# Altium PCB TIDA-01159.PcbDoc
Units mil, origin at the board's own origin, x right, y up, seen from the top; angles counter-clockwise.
Board outline 1460.63 x 1181.1 mil, 2 copper layers (Top Layer, Bottom Layer), stack 62 mil thick; 34 components, 21 nets, 78 pads, 9 vias.
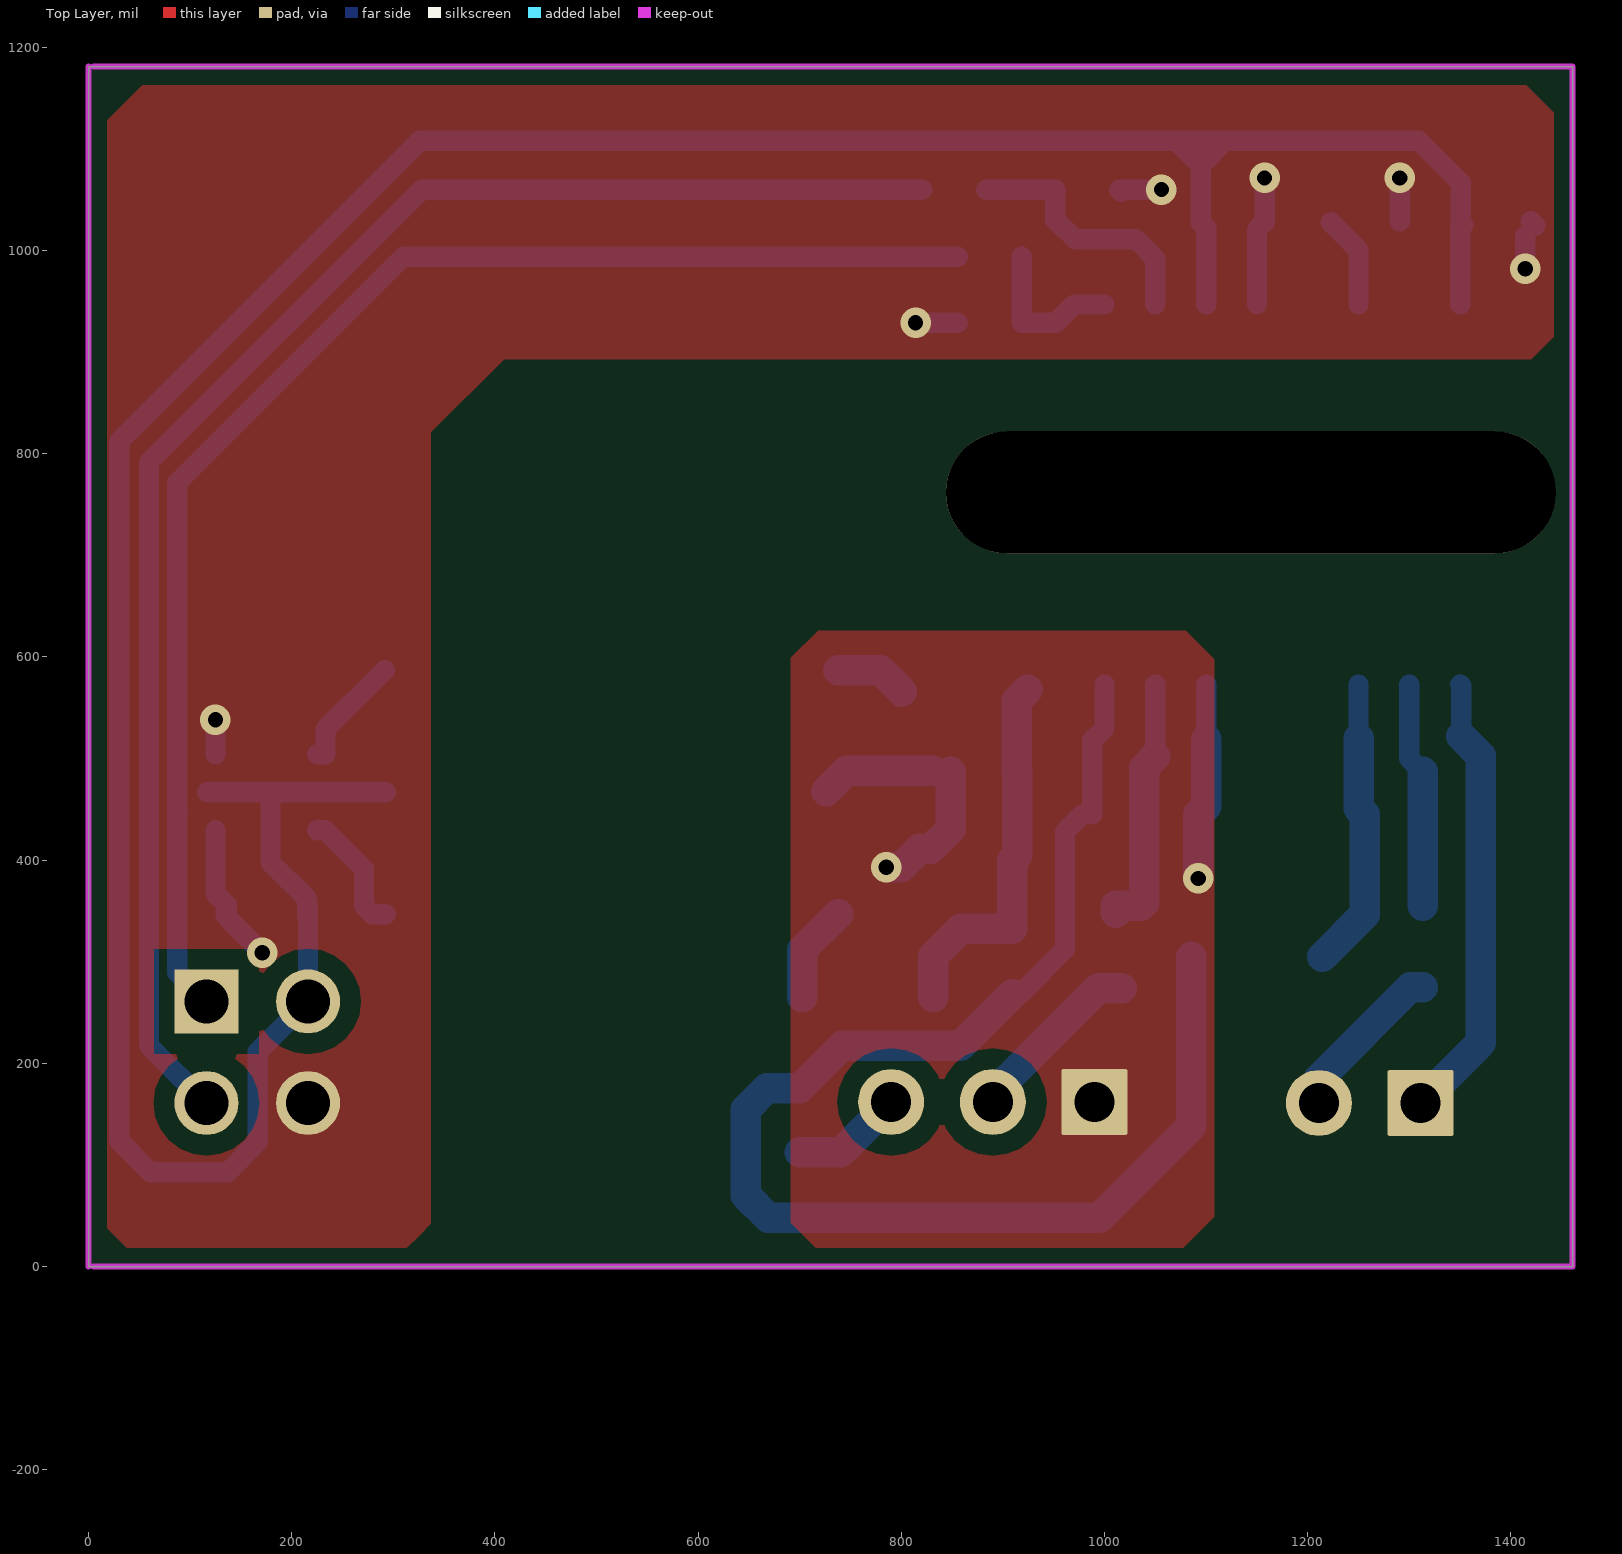
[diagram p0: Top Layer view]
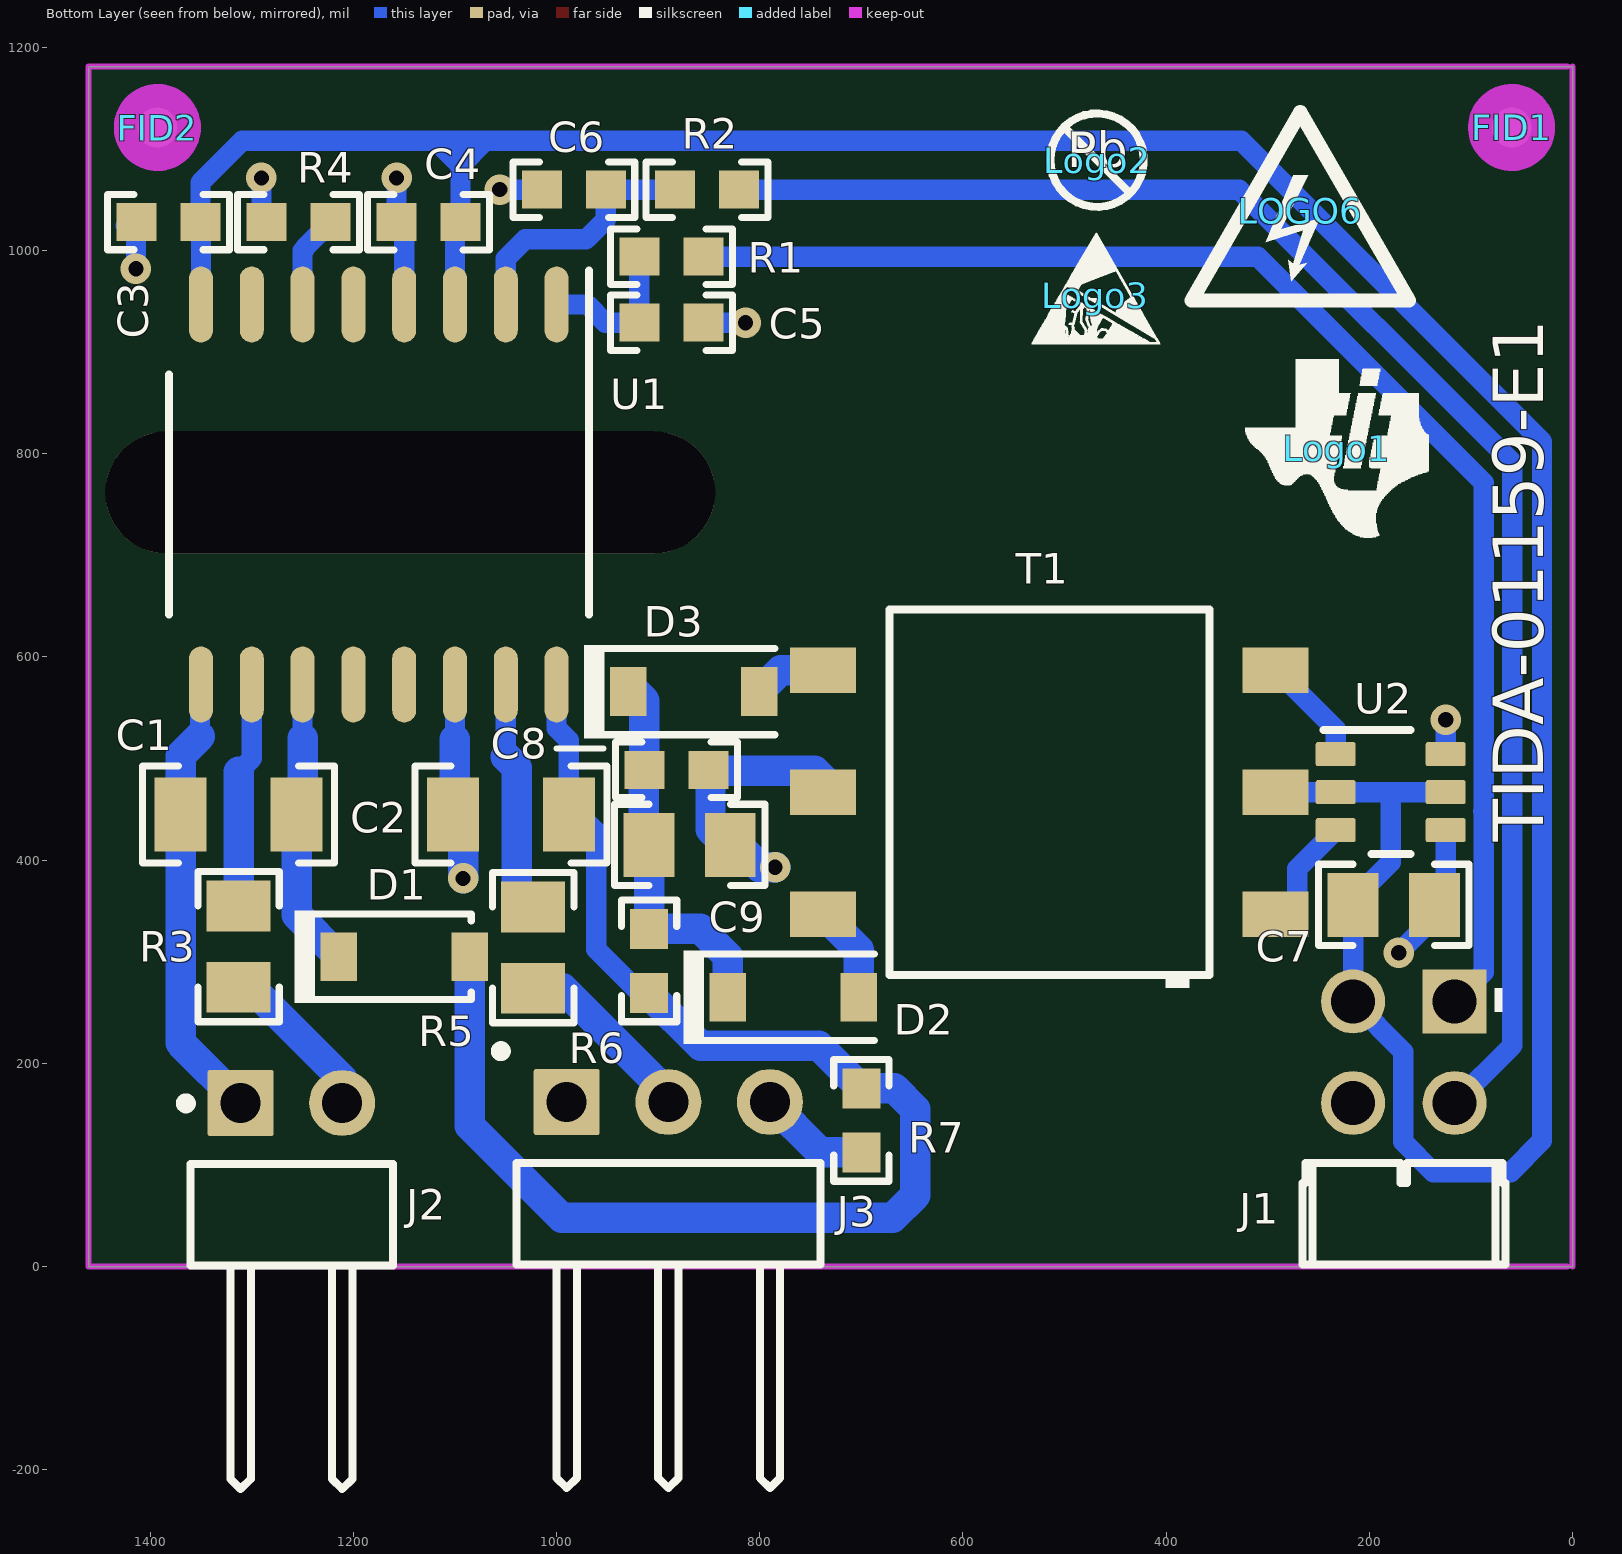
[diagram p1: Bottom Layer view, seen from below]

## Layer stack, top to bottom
Top Solder: solder mask 0.4, Solder Resist, Dk 3.5
Top Layer: signal copper 1.4
Dielectric1: core 59.2, FR-4 High Tg, Dk 4.8
Bottom Layer: signal copper 1.4
Bottom Solder: solder mask 0.4, Solder Resist, Dk 3.5

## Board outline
0,0 0,1181.1 1460.63,1181.1 1460.63,0

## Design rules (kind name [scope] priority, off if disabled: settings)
AcuteAngle [All] p1: minimum=4.50000000000000E+0001 checktracksonly=FALSE
AssemblyTestPointUsage [All] p1: valid=2
Clearance Clearance_Keepouts [((IsTrack Or IsArc) And Not InPoly) And IsFree and IsKeepOut vs ((IsTrack Or IsArc) And Not InPoly) And IsFree and IsKeepOut] p1: gap=20
Clearance Clearance_BoardEdge_MountingHoles [OnCopper and InComponentClass('Mounting Holes') vs IsKeepOut] p2: gap=40
Clearance Clearance_BoardEdge_Poly [OnCopper and InPoly vs IsKeepOut] p3: gap=15
Clearance Clearance_BoardEdge [OnCopper and Not InComponentClass('Logo') and not InComponentClass('FiducialMark') and not InRegion(1000,500,4000,800) and Not IsKeepout vs IsKeepOut] p4: gap=15
Clearance Clearance_Poly [InPolygon] p5: gap=20
Clearance [All] p6: gap=7.87
ComponentClearance ComponentClearance_MountingHoles_FiducialMarks [InComponentClass('Mounting Holes') vs InComponentClass('FiducialMark')] p1: gap=50 collisioncheckmode=3 verticalgap=10 showdistances=FALSE
ComponentClearance ComponentClearance_Shunt [InComponentClass('Header') vs InComponentClass('Shunt')] p2: gap=0 collisioncheckmode=3 verticalgap=0 showdistances=FALSE
ComponentClearance ComponentClearance_Logo [InComponentClass('Logo')] p3: gap=50 collisioncheckmode=3 verticalgap=10 showdistances=FALSE
ComponentClearance ComponentClearance_ScrewToNut [(HasFootprint('NY PMS 440 0025 PH')) vs (HasFootprint('Keystone_1902C'))] p4: gap=5 collisioncheckmode=3 verticalgap=10 showdistances=FALSE
ComponentClearance ComponentClearance_MountingHoles [InComponentClass('Mounting Holes')] p5: gap=200 collisioncheckmode=3 verticalgap=100000 showdistances=FALSE
ComponentClearance ComponentClearance_SmallPassives [HasFootprint('0201*') or HasFootprint('0402*') or HasFootprint('0508') or HasFootprint('0603*') or HasFootprint('0612') or HasFootprint('0805*') or HasFootprint('0815*') or HasFootprint('0830*') or HasFootprint('1206*') or HasFootprint('1210*') or HasFootprint('1808*') or HasFootprint('1812*') or HasFootprint('1825*') or HasFootprint('2010*') or HasFootprint('2220*') or HasFootprint('2225*') or HasFootprint('2512*') or HasFootprint('2728*') or HasFootprint('3518*') vs HasFootprint('0201*') or HasFootprint('0402*') or HasFootprint('0508') or HasFootprint('0603*') or HasFootprint('0612') or HasFootprint('0805*') or HasFootprint('0815*') or HasFootprint('0830*') or HasFootprint('1206*') or HasFootprint('1210*') or HasFootprint('1808*') or HasFootprint('1812*') or HasFootprint('1825*') or HasFootprint('2010*') or HasFootprint('2220*') or HasFootprint('2225*') or HasFootprint('2512*') or HasFootprint('2728*') or HasFootprint('3518*')] p6: gap=20 collisioncheckmode=3 verticalgap=10 showdistances=FALSE
ComponentClearance ComponentClearance_THtoSMT [IsThruComponent vs IsSMTComponent] p7: gap=20 collisioncheckmode=3 verticalgap=20 showdistances=FALSE
ComponentClearance ComponentClearance_THtoTH [IsThruComponent vs IsThruComponent] p8: gap=10 collisioncheckmode=3 verticalgap=10 showdistances=FALSE
ComponentClearance [All] p9: gap=20 collisioncheckmode=3 verticalgap=10 showdistances=FALSE
DiffPairsRouting [All] p1: maxlimit=100 minlimit=10 mostfreqgap=10 toplayer_minwidth=15 toplayer_maxwidth=15 toplayer_prefwidth=15 bottomlayer_minwidth=15 bottomlayer_maxwidth=15 bottomlayer_prefwidth=15 maxuncoupledlength=1000
FabricationTestPointUsage TestPointUsage [All] p1: valid=2 allowmultiple=FALSE
FabricationTestpoint Testpoint [All] p1: side=3 testpointundercomponent=TRUE minsize=40 maxsize=100 preferedsize=60 minholesize=0 maxholesize=40 preferedholesize=32 testpointgrid=1 allowsidetop=TRUE allowsidebottom=TRUE usegrid=TRUE gridtolerance=0.01
FanoutControl Fanout_LCC [IsLCC] p1: bgadir=Out bgaviamode=Centered fanoutstyle=Auto fanoutdirection=Alternating viagrid=1 // Fanout_LCC (Default Rule)
FanoutControl Fanout_BGA [IsBGA] p2: bgadir=Out bgaviamode=Centered fanoutstyle=Auto fanoutdirection=Alternating viagrid=1 // Fanout_BGA (Default Rule)
FanoutControl Fanout_Default [All] p4: bgadir=Out bgaviamode=Centered fanoutstyle=Auto fanoutdirection=Alternating viagrid=1 // Fanout_Default (Default Rule)
FanoutControl Fanout_Small [(CompPinCount < 5)] p5: bgadir=Out bgaviamode=Centered fanoutstyle=Auto fanoutdirection=OutThenIn viagrid=1 // Fanout_Small (Default Rule)
HoleSize [All] p1: absolutevalues=TRUE maxlimit=251 minlimit=8 maxpercent=80.000 minpercent=20.000
MinimumAnnularRing MinimumAnnularRing_ThermalPadVias [IsVia and InAnyComponent] p1: minimumring=5.91
MinimumAnnularRing [All] p2: minimumring=6
MinimumSolderMaskSliver MinimumSolderMaskSliver_Logo [InComponentClass('Logo') vs InComponentClass('Logo')] p1: minsoldermaskwidth=0.7
MinimumSolderMaskSliver [All] p2: minsoldermaskwidth=3.94
PlaneConnect [All] p1: planeconnectstyle=Relief reliefexpansion=10 reliefentries=4 reliefconductorwidth=10 reliefairgap=10
PolygonConnect [All] p1: connectstyle=Direct reliefconductorwidth=10 reliefentries=4 polygonreliefangle="90 Angle" airgapwidth=10
RoutingVias ThermalPadVias [IsVia and InAnyComponent] p1: holewidth=7.87 width=19.68 viastyle="Through Hole" minholewidth=7.87 minwidth=19.68 maxholewidth=12.99 maxwidth=23.62
RoutingVias [All] p2: holewidth=12 width=24 viastyle="Through Hole" minholewidth=7.87 minwidth=26 maxholewidth=40 maxwidth=65
SilkToBoardRegionClearance [Not ((IsComment or IsDesignator) And (Hide <> 'False')) and not InRegion(1000,500,4000,800)] p1:
SilkToSilkClearance SilkToSilkClearance_Pb-FreeLogo [(HasFootprint('Pb-Free_Overlay_Medium') OR HasFootprint('Pb-Free_Overlay_Small')) vs (HasFootprint('Pb-Free_Overlay_Medium') OR HasFootprint('Pb-Free_Overlay_Small'))] p1: silktosilkclearance=0
SilkToSilkClearance [All] p2: silktosilkclearance=4
SilkToSolderMaskClearance "Silk to Solder Mask Opening" [All] p1: minsilkscreentomaskgap=4 clearancetoexposedcopper=FALSE
SolderMaskExpansion [All] p1: expansion=1.97
UnpouredPolygon [All] p1: allowunpoured=FALSE
Width [All] p1: maxlimit=40 minlimit=6 preferedwidth=20 checkconnectedcopper=TRUE
14 further rules are at their usual default settings.

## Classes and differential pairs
component class Header: J1
component class Logo: Logo1
component class TIDA-01159_Hardware: FID1 FID2 Logo1 Logo2 Logo3 LOGO6 ZZ2 ZZ3 ZZ4
component class FiducialMark: FID1 FID2
component class AssemblyNote: ZZ2 ZZ3 ZZ4
component class TIDA-01159_Sheet1: C1 C2 C3 C4 C5 C6 C7 C8 C9 D1 D2 D3 J1 J2 J3 R1 R2 R3 R4 R5 R6 R7 T1 U1 U2

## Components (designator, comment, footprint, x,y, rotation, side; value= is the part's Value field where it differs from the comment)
C1 "CGA5L3X7T2E224K160AE" 1206 1313,445 r0 bottom
C2 "CGA5L3X7T2E224K160AE" 1206 1045,445 r0 bottom
C3 "885012106018" 0603 1382,1028 r180 bottom
C4 "C0603X104K3RACTU" 0603 1126,1028 r0 bottom
C5 "06035A220JAT2A" 0603 887,929 r180 bottom
C6 "06035A220JAT2A" 0603 983,1060 r0 bottom
C7 "GRM21BZ71E106KE15L" 0805_HV 176,356 r0 bottom
C8 "8.850122061e+011" 0603 882,489 r0 bottom
C9 "GRM21BZ71E106KE15L" 0805_HV 869,415 r0 bottom
D1 "UFM15PL-TP" SOD-123FL 1150,305 r180 bottom
D2 "1N5819HW-7-F" SOD-123 767,265 r180 bottom
D3 "1N5819HW-7-F" SOD-123 865,566 r180 bottom
FID1 "Fiducial" Fiducial10-20 60,1121.1 r90 bottom
FID2 "Fiducial" Fiducial10-20 1392.95,1121.1 r180 bottom
J1 "61300421021" Wurth_61300421021 166,211 r270 bottom
J2 "TSW-102-08-G-S-RA" TSW-102-08-G-S-RA 1259,162 r180 bottom
J3 "TSW-103-08-G-S-RA" TSW-103-08-G-S-RA 890,162 r180 bottom
Logo1 "Texas Instruments" TI_Symbol_Overlay_Small 232,805 r180 bottom
Logo2 "Pb-Free Symbol" Pb-Free_Overlay_Small 468,1089 r180 bottom
Logo3 "ESD Susceptible" ESD_Overlay_Small 470,956 r180 bottom
LOGO6 "DANGER HIGH VOLTAGE" IEC_HighVoltage_Small 268,1039 r180 bottom
R1 "CRCW0603100RFKEA" 0603 887,994 r0 bottom
R2 "CRCW0603100RFKEA" 0603 852,1060 r0 bottom
R3 "CRCW08050000Z0EA" 0805_HV 1313,315 r270 bottom
R4 "RT0603BRD074K75L" 0603 1254,1028 r180 bottom
R5 "CRCW08050000Z0EA" 0805_HV 1023,314 r270 bottom
R6 "CRCW06030000Z0EA" 0603 909,301 r270 bottom
R7 "CRCW06030000Z0EA" 0603 700,144 r270 bottom
T1 "750342879" WURTH_750342879 515,467 r0 bottom
U1 "UCC21520DW" DW0016A_N 1175,760 r270 bottom
U2 "SN6505BDBVR" DBV0006A_N 179,467 r180 bottom
ZZ2 "These assemblies are ESD sensitive, ESD precautions shall be observed." AssemblyNote -80,1683.6 r0 top
ZZ3 "These assemblies must be clean and free from flux and all contaminants. Use of no clean flux is not acceptable." AssemblyNote -80,1595.05 r0 top
ZZ4 "These assemblies must comply with workmanship standards IPC-A-610 Class 2, unless otherwise specified." AssemblyNote -80,1506.49 r0 top

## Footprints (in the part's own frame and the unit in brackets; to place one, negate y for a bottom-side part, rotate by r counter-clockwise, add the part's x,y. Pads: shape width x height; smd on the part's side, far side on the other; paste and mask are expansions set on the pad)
0603 [mm] "0603 from SM-752 data"
  rect 1x0.95 smd: 1(-0.8,0) 2(0.8,0)
  silkscreen extent -1.52,-0.69 1.52,0.69, body extent -0.87,-0.47 0.87,0.47, height 1
0805_HV [mil] "0805 with 30mil clearance between pads"
  rect 50x63 smd: 1(-40,0) 2(40,0)
  silkscreen extent -74,-40 74,40, body extent -43,-29 43,29, height 57
1206 [mm] "1206 from SM-752 data"
  rect 1.3x1.85 smd: 1(-1.45,0) 2(1.45,0)
  silkscreen extent -2.4,-1.21 2.4,1.21, body extent -1.7,-0.9 1.7,0.9, height 1.35
AssemblyNote [mil] "Assembly Note"
DBV0006A_N [mm] "SOT23, 6-Leads, Body 2.9x1.6mm, Pitch 0.95mm, Lead Span 2.8mm, IPC Medium Density"
  rrect17% 1x0.6 smd: 1(-1.375,0.95) 2(-1.375,0) 3(-1.375,-0.95) 4(1.375,-0.95) 5(1.375,0) 6(1.375,0.95)
  silkscreen extent -1.68,-1.55 0.5,1.55, body extent -1.42,-1.46 1.42,1.46, height 1.12
DW0016A_N [mm] "SOIC, 16-Leads, Body 10.3x7.5mm, Pitch 1.27mm, IPC Medium Density"
  oval 1.9x0.6 smd: 1(-4.75,4.445) 2(-4.75,3.175) 3(-4.75,1.905) 4(-4.75,0.635) 5(-4.75,-0.635) 6(-4.75,-1.905) 7(-4.75,-3.175) 8(-4.75,-4.445) 9(4.75,-4.445) 10(4.75,-3.175) 11(4.75,-1.905) 12(4.75,-0.635) 13(4.75,0.635) 14(4.75,1.905) 15(4.75,3.175) 16(4.75,4.445)
  silkscreen extent -5.6,-5.25 3,5.25, body extent -5.14,-5.13 5.14,5.13, height 2.54
ESD_Overlay_Small [mil]
  silkscreen extent -62,-48 64,61
Fiducial10-20 [mm]
  round 1 smd mask+0.5: 1(0,0)
  Top Layer keep-out circle w1.178: c0,0 r0.5
IEC_HighVoltage_Small [mil]
  silkscreen extent -107,-88 107,97
Pb-Free_Overlay_Small [mil]
  silkscreen extent -46,-46 46,46
SOD-123 [mm] "On Semi recommended land pattern"
  rect 0.915x1.22 smd: 1(-1.637,0) 2(1.637,0)
  silkscreen extent -2.74,-1.17 2.03,1.17, body extent -1.93,-0.9 1.93,0.9, height 1.35
SOD-123FL [mm] "Copied from SOD-123"
  rect 0.915x1.22 smd: 1(-1.637,0) 2(1.637,0)
  silkscreen extent -2.74,-1.16 1.68,1.16, body extent -1.9,-0.9 1.9,0.9, height 1
TI_Symbol_Overlay_Small [mil]
  silkscreen extent -90,-88 91,88
TSW-102-08-G-S-RA [mm] "Samtec Right Angle Header"
  rrect6% 1.65x1.65 hole 1: 1(-1.321,-0.025)
  round 1.65 hole 1: 2(1.219,-0.025)
  silkscreen extent -2.82,-9.68 2.49,0.09, body extent -2.59,-9.93 2.49,0.29, height 3.05
TSW-103-08-G-S-RA [mm] "Samtec Right Angle Header"
  rrect6% 1.65x1.65 hole 1: 1(-2.54,0)
  round 1.65 hole 1: 2(0,0) 3(2.54,0)
  silkscreen extent -4.31,-9.65 3.81,1.39, body extent -3.81,-9.91 3.81,0.32, height 3.05
WURTH_750342879 [mm] "SMD, 6-Leads, Body 9.14x8mm, Pitch 3.05mm"
  rect 1.649x1.14 smd: 1(-5.655,3.05) 2(-5.655,0) 3(-5.655,-3.05) 4(5.655,-3.05) 5(5.655,0) 6(5.655,3.05)
  silkscreen extent -4,-4.57 4,4.9, body extent -6.35,-4.57 6.35,4.57, height 7.83
Wurth_61300421021 [mm] "Header, 2.54mm, 2x2, R/A, TH"
  rect 1.6x1.6 hole 1.1: 1(-1.27,1.27)
  round 1.6 hole 1.1: 2(1.27,1.27) 3(-1.27,-1.27) 4(1.27,-1.27)
  silkscreen extent -1.6,-2.54 5.31,2.54, body extent -1.59,-2.54 11.31,2.54, height 5.08

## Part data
C1 C2: "CAP, CERM, 0.22 µF, 250 V, +/- 10%, X7T, 1206"
C3: "CAP, CERM, 2.2 µF, 16 V, +/- 20%, X5R, 0603"
C4: "CAP, CERM, 0.1 µF, 25 V, +/- 10%, X7R, 0603"
C5 C6: "CAP, CERM, 22 pF, 50 V, +/- 5%, C0G/NP0, 0603"
C7 C9: "CAP, CERM, 10 µF, 25 V, +/- 10%, X7R, 0805"
C8: "CAP, CERM, 0.1 µF, 50 V, +/- 10%, X7R, 0603"
D1: "Diode, Ultrafast, 600 V, 1 A, SOD-123FL"
D2 D3: "Diode, Schottky, 40 V, 1 A, SOD-123"
FID1 FID2: "Fiducial mark.  There is nothing to buy or mount."
J1: "Header, 2.54mm, 2x2, Gold, R/A, TH"
J2: "Header, 100mil, 2x1, Gold, R/A, TH"
J3: "Header, 100mil, 3x1, Gold, R/A, TH"
Logo1: library part TI_Logo, "Texas Instrument Corporate Signature"
Logo2: library part Pb-Free
Logo3: library part ESD_Susceptible, "ESD Susceptible Symbol"
LOGO6: library part IEC_HighVoltage, "IEC 61010-1 High Voltage Warning"
R1 R2: "RES, 100, 1%, 0.1 W, 0603"
R3 R5: "RES, 0, 5%, 0.125 W, 0805"
R4: "RES, 4.75 k, 0.1%, 0.1 W, 0603"
R6 R7: "RES, 0, 5%, 0.1 W, 0603"
T1: "Transformer, 50 uH, SMT"
U1: "4A/6A, 5KVrms Dual Isolated-channel Universal Gate Driver, DW0016A"
U2: "LOW-NOISE 1A TRANSFORMER DRIVERS FOR ISOLATED POWER SUPPLIES, DBV0006A"
ZZ2 ZZ3 ZZ4: library part AssemblyNote

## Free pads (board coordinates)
  oval 600x120 hole 120 slot 600 at 0 deg unplated mask+5: 0(1144,762)

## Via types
v1: diameter 30, hole 15, Top Layer to Bottom Layer, tented both sides, 9 vias

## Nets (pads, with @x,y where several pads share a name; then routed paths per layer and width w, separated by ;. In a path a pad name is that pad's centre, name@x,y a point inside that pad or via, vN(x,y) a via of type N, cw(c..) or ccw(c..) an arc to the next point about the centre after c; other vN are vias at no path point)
AUX_12V: C2.1 D1.2 R6.2 R7.1 U1.16 | length 1378.7
  Bottom Layer w20: R6.2@918.35,269.5 961,312.16 961,428.09 C2.1@977.91,445 ; C2.1 987.91,517.91 1000,530 U1.16
  Bottom Layer w30: R6.2@909,268.16 858.2,217.35 741.86,217.35 R7.1 667.5,175.5 647,155 647,70 669,48 995,48 1085.53,138.53 D1.2
GD_HS: J2.2 R3.2 | length 163.3
  Bottom Layer w30: J2.2 1211,185 1301,275 R3.2
GD_LS: J3.2 R5.2 | length 178.1
  Bottom Layer w30: J3.2 890,170 994,274 R5.2@1017,274
HV_AUX_12V: J3.3 R7.2 | length 110.5
  Bottom Layer w30: R7.2 740.5,112.5 J3.3
HV_GND: C2.2 C8.1 C9.1 J3.1 T1.5 U1.14 | length 433.3
  Bottom Layer w20: 1100,519 U1.14
  Bottom Layer w30: T1.5@725.92,468 745.92,488 C8.1@831.5,488 ; v1(785,393) 800,393 818,411 C9.1@817.5,411.5 ; C9.1@829,411 848.5,430.5 C8.1@848.5,487 ; v1(1092.09,382.09) 1092.09,445 1100,452.91 1100,519
HV_HS_PWM: J1.1 R1.1 | length 1383.3
  Bottom Layer w20: J1.1 87.31,289.69 87.31,447.64 87.97,448.3 87.31,448.96 87.31,771.43 309.87,994 R1.1
HV_LS_PWM: J1.2 R2.1 | length 1526.2
  Bottom Layer w20: J1.2 59.43,217.57 59.43,791.43 328,1060 R2.1
HV_SNODE: C1.2 J2.1 U1.9 | length 444.8
  Bottom Layer w20: U1.9 1351,571.99 1351,522
  Bottom Layer w30: J2.1 1370.09,220.09 C1.2 1370.09,502.91 1351,522
LV_AUX_5V: C3.2 C4.1 C7.2 J1.3 T1.2 U1.3 U1.8 U2.2 U2.5 | length 3228.5
  Bottom Layer w20: U2.5@116.87,467 U2.5 179,467 ; C7.2@215,345 215,362 179,398 179,467 ; C7.2 J1.3 166.63,211.63 166.63,122.63 137,93 60.84,93 30.13,123.72 30.13,812.13 326,1108 1070.02,1108 ; T1.2 U2.2 179,467 ; U1.3 1100,1022.5 C4.1 1094.5,1083.51 ; U1.8@1350.5,947.5 U1.8 1350,1022.5 C3.2@1353,1025.5 ; C3.2 1350.5,1066.74 1309.25,1108 1118.99,1108 ; 1070.02,1108 1096,1108 ; 1070.02,1108 1094.5,1083.51 ; 1094.5,1083.51 1118.99,1108 ; 1094.5,1083.51 1094.5,1106.5 1096,1108 ; 1096,1108 1118.99,1108
NetC1_1: C1.1 D1.1 U1.11 | length 287.6
  Bottom Layer w20: 1250,520 U1.11
  Bottom Layer w30: D1.1 1255.91,346.45 C1.1 1250,450.91 1250,520
NetC5_1: C5.1 R1.2 U1.1 | length 154
  Bottom Layer w20: R1.2 C5.1 952,929 970.01,947.01 U1.1
NetC6_1: C6.1 R2.2 U1.2 | length 256.9
  Bottom Layer w20: R2.2 C6.1 951.5,1030.5 971,1011 1031,1011 1050,992 U1.2
NetC8_2: C8.2 C9.2 D2.1 D3.1 R6.1 | length 371.3
  Bottom Layer w30: D2.1 831.47,305.47 858.5,332.5 R6.1 909,400 914,405 C8.2@914,489 ; C8.2 913.5,557.03 D3.1@924.47,568
NetD2_2: D2.2 T1.6 | length 96.5
  Bottom Layer w30: D2.2 702.53,311.82 T1.6
NetD3_2: D3.2 T1.4 | length 71.6
  Bottom Layer w30: T1.4 779.45,587.08 D3.2
NetR3_1: R3.1 U1.10 | length 223.4
  Bottom Layer w20: U1.10 1300,500 1313,487
  Bottom Layer w30: R3.1 1313,487
NetR4_2: R4.2 U1.6 | length 92.4
  Bottom Layer w20: R4.2 1247.94,1002.57 1247.94,1001.9 1250,999.83 U1.6
NetR5_1: R5.1 U1.15 | length 253.4
  Bottom Layer w20: 1050,502 U1.15
  Bottom Layer w30: R5.1@1011,348.47 R5.1@1014.27,351.73 ; R5.1@1011,355 1036,355 1039,358 1039,491 1050,502
NetT1_1: T1.1 U2.3 | length 123
  Bottom Layer w20: U2.3@225.13,429.6 U2.3 271,391.73 271,355 279.08,346.92 T1.1
NetT1_3: T1.3 U2.1 | length 114.8
  Bottom Layer w20: U2.1@225.13,504.4 U2.1 233.13,528.85 T1.3@291.36,587.08
SGND: C3.1 C4.2 C5.2 C6.2 C7.1 J1.4 R4.1 U1.4 U2.4 U2.6 | length 480.2
  Bottom Layer w20: U2.4 124.87,367.13 C7.1@135,357 ; U2.6 v1(124.87,538.13) ; C7.1@135,345 C7.1@135,357 ; v1(171,309) 136,344 C7.1 C7.1@135,357 ; v1(814,929) C5.2 ; C6.2@1016.5,1058 C6.2 v1(1056,1060) ; U1.4 1150,1020.5 C4.2 v1(1157.5,1071.5) ; R4.1@1290.5,1029 v1(1290.5,1071.5) ; v1(1414,982) C3.1@1414,1014.5 ; C3.1@1419.5,1029 C3.1@1424,1024.5
pads on no net: FID1.1 FID2.1 U1.5 U1.7 U1.12 U1.13

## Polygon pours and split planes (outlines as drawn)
no net on Top Solder "M9 Title Sheet-No Net" (solid): 1280,827.04 1280,697 1382.95,697 1382.95,807 1382.95,826.98
no net on Top Solder "M9 Title Sheet-No Net" (solid): 1460,827 1460,697 576,697 576,0 449,0 449,827
no net on Bottom Solder "M9 Title Sheet-No Net" (solid): 1382.95,827 1280,827 1280,697 1382.95,697 1382.95,807
no net on Bottom Solder "M9 Title Sheet-No Net" (solid): 448,827 1460.63,827 1460.63,697 578,697 578,0.46 448,0.46
SGND on Top Layer "M9 Title Sheet-No Net" (solid, remove dead copper, pour order 9): 5,112 5,51 56,0 65,0 295,0 325,30 337,42 337,386 337,821 409,893 881.16,893 1420,893 1447,920 1447,1131 1397,1181 71,1181 5,1115
HV_GND on Top Layer "M9 Title Sheet-No Net" (solid, remove dead copper, pour order 8): 691,599 691,43 734,0 1059,0 1108,49 1108,598 1080,626 921,626 718,626

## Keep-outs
Keep-Out Layer:
  lines w6: 0,0 0,1181.1 ; 5,0 1460.63,0 1460.63,1181.1 5,1181.1
  text ".Layer_Name" at 362,-1164 h60

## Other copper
Top Layer:
  text ".Layer_Name" at 362,-1164 h60
Bottom Layer:
  text ".Layer_Name" at 362,-1164 h60

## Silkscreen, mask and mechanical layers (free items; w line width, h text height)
Top Overlay:
  text ".Layer_Name" at 362,-1164 h60
Bottom Overlay:
  lines w6: 954,510 1000,510
  text "TIDA-01159-E1" at 29,418 h50 r270
  text ".Layer_Name" at 362,-1164 h60
Top Paste:
  text ".Layer_Name" at 362,-1164 h60
Bottom Paste:
  text ".Layer_Name" at 362,-1164 h60
Top Solder:
  text ".Layer_Name" at 362,-1164 h60
  text ".Layer_Name" at 362,-1164 h60
Bottom Solder:
  text ".Layer_Name" at 362,-1164 h60
Drill Guide:
  text ".Layer_Name" at 362,-1164 h60
M1 Board Outline:
  the board outline again, w10
M2 Board Dimensions:
  rectangle: -215,-580.51 -90,-455.51
  rectangle: -90,-705.51 285,-580.51
  lines w7: -215,-580.51 785,-580.51 ; -90,-705.51 -90,-455.51 ; 35,-705.51 35,-455.51 ; 285,-705.51 285,-455.51 ; 535,-705.51 535,-455.51 ; -215,-705.51 785,-705.51 785,-455.51 -215,-455.51 -215,-705.51
M3 3D STEP Top:
  text ".Layer_Name" at 362,-1164 h60
M4 3D STEP Bottom:
  text ".Layer_Name" at 362,-1164 h60
M5 Assembly Top:
  lines w10: -507,-1235.68 6093,-1235.68 ; -507,-1032.34 6095,-1032.34 ; -507,-829.01 -507,-1439.01 3498,-1439.01 6095,-1439.01 6095,-829.01 -506.5,-829.01 -506.5,-1439.01 1069,-1439.01 ; 1958,-1439.01 1958,-829.01 ; 3225,-1032.34 3225,-829.01 ; 4065,-1032.34 4065,-829.01 ; 4687,-1445.51 4687,-1242.68
  text "COMPONENTS MARKED 'DNP' SHOULD NOT BE POPULATED." at 938.5,-624.01 h60
  text "ASSEMBLY VARIANT:" at 938,-739.51 h60
  text ".VariantName" at 1974,-739.51 h60
  text "PCB VIEWED FROM TOP SIDE" at -443.5,-961.18 h60
  text "BOARD #:" at 2033,-961.18 h60
  text ".PRJ_Number" at 2578.5,-961.18 h60
  text "REV:" at 3423,-961.18 h60
  text ".PCB_Rev" at 3714.5,-961.18 h60
  text "SVN REV:" at 4261,-961.18 h60
  text ".VersionControl_RevNumber" at 4767,-961.18 h60
  text ".LAyer_Name" at 332,-1161 h60
  text "TID #:" at 2033,-1164.51 h60
  text ".TID" at 2578.5,-1164.51 h60
  text "PLOT NAME =" at -443.5,-1369.85 h60
  text ".plot_File_Name" at 362,-1369.85 h60
  text "GENERATED    :" at 2035,-1369.85 h60
  text ".Print_Date" at 2904.5,-1369.85 h60
  text ".Print_Time" at 3633.5,-1369.85 h60
  text "TEXAS INSTRUMENTS" at 4898,-1369.85 h60
M6 Assembly Bottom:
  lines w10: -507.5,-1032.84 6094.5,-1032.84 ; -505.5,-1236.18 6094.5,-1236.18 ; 900.5,-1446.01 900.5,-1243.18 ; 1522.5,-1032.84 1522.5,-829.51 ; 2362.5,-1032.84 2362.5,-829.51 ; 3629.5,-1439.51 3629.5,-829.51 ; 4518.5,-1439.51 6094,-1439.51 6094,-829.51 -507.5,-829.51 -507.5,-1439.51 2089.5,-1439.51 6094.5,-1439.51 6094.5,-829.51
  text "COMPONENTS MARKED 'DNP' SHOULD NOT BE POPULATED." at 5887,-623.51 h60
  text ".VariantName" at 4843,-739.51 h60
  text "ASSEMBLY VARIANT:" at 5882,-739.51 h60
  text ".VersionControl_RevNumber" at 820.5,-961.68 h60
  text "SVN REV:" at 1326.5,-961.68 h60
  text ".PCB_Rev" at 1873,-961.68 h60
  text "REV:" at 2164.5,-961.68 h60
  text ".PRJ_Number" at 3009,-961.68 h60
  text "BOARD #:" at 3554.5,-961.68 h60
  text "PCB VIEWED FROM BOTTOM SIDE" at 6031,-961.68 h60
  text ".LAyer_Name" at 5302,-1150 h60
  text ".TID" at 3009,-1165.01 h60
  text "TID #:" at 3554.5,-1165.01 h60
  text "TEXAS INSTRUMENTS" at 689.5,-1370.35 h60
  text ".Print_Time" at 1954,-1370.35 h60
  text ".Print_Date" at 2683,-1370.35 h60
  text "GENERATED    :" at 3552.5,-1370.35 h60
  text ".plot_File_Name" at 5225.5,-1370.35 h60
  text "PLOT NAME =" at 6031,-1370.35 h60
M9 Title Sheet:
  drawing of 57 lines, arcs and shapes, not listed
  text "1" at 524.84,7730.99 h70
  text "2" at 3020.5,7730.99 h70
  text "3" at 5509.84,7730.99 h70
  text "4" at 8016.51,7730.99 h70
  text "5" at 10515.5,7730.99 h70
  text "6" at 13020.5,7730.99 h70
  text "A" at -631.5,6587.99 h70
  text "A" at 14168.5,6587.99 h70
  text "B" at -631.5,4207.99 h70
  text "B" at 14168.5,4207.99 h70
  text "C" at -631.5,1832.99 h70
  text "C" at 14168.5,1832.99 h70
  text "PROJECT TITLE:" at 11128.5,-28.01 h45
  text ".PRJ_Title" at 11178.5,-161.34 h70
  text "DESIGNED FOR:" at 11128.5,-329.01 h45
  text ".PRJ_Customer" at 11178.5,-469.01 h70
  text "D" at -631.5,-537.01 h70
  text "D" at 14168.5,-537.01 h70
  text "FILE NAME:" at 11128.5,-629.01 h45
  text ".PCB_File_Name_No_Path" at 11178.5,-749.01 h70
  text "Texas Instruments (TI) and/or its licensors do not warrant the accuracy or completeness of this specification" at 6159,-910.85 h45
  text "ENGINEER:" at 11128.5,-919.01 h45
  text "LAYOUT BY:" at 12633.5,-919.01 h45
  text "or any information contained therein. TI and/or its licensors do not warrant that this design will meet" at 6114.02,-1023.52 h45
  text ".PRJ_Engineer" at 11178.5,-1074 h70
  text ".PCB_Layout" at 12684,-1074 h70
  text "the specifications, will be suitable for your application or fit for any particular purpose, or will operate in" at 6114.02,-1136.18 h45
  text "ALTIUM DESIGNER VERSION:" at 12633.5,-1229.01 h45
  text "an implementation. TI and/or its licensors do not warrant that the design is production worthy. You should" at 6114.02,-1248.85 h45
  text "completely validate and test your design implementation to confirm the system functionality for your application." at 6159,-1361.51 h45
  text ".print_Scale" at 11178.5,-1362.34 h70
  text ".Application_BuildNumber" at 12684,-1362.34 h70
  text "1" at 524.84,-1569.01 h70
  text "2" at 3020.5,-1569.01 h70
  text "3" at 5509.84,-1569.01 h70
  text "4" at 8016.51,-1569.01 h70
  text "5" at 10515.5,-1569.01 h70
  text "6" at 13020.5,-1569.01 h70
M10 Fab Notes:
  drawing of 191 lines, arcs and shapes, not listed
  text "DESIGN INFORMATION" at 12171.52,6384.49 h60
  text "(REFER ALSO ARRAY/PANEL PROFILING INFORMATION)" at 11809.96,6222.77 h60
  text "BOARD SIZE" at 11123.96,6218.49 h60
  text "X" at 12091.96,6090.67 h60
  text "30MM" at 12327.5,6083.49 h60
  text "37.1MM" at 11578,6080 h60
  text "Number of Layers :" at 11541.96,5983.49 h60
  text "2" at 12636.77,5973.49 h60
  text "MIN. TRACK WIDTH:" at 11541.96,5844.49 h60
  text "20" at 12611.5,5844.89 h60
  text "MIL" at 12792.96,5844.49 h60
  text "MIN. CLEARANCE:" at 11541.96,5712.49 h60
  text "7.87" at 12560,5712 h60
  text "MIL" at 12810.5,5685.89 h60
  text "MIN. VIA PAD SIZE:" at 11541.96,5580.49 h60
  text "30" at 12622.5,5580.89 h60
  text "MIL" at 12810.5,5557.89 h60
  text "0.19mm (7.5MIL)" at 12236.96,5438.78 h60
  text "EXTERNAL" at 12973.5,5438.89 h60
  text "MINIMUM ANNULAR RING" at 11212.73,5434.49 h60
  text "PER" at 11412.73,5316.49 h60
  text "IPC-D-275 CLASS 2 LEVEL C" at 11632.73,5316.49 h60
  text "MIL, HOLES" at 13120.96,5204.2 h60
  text "+/-" at 12728.5,5203.49 h60
  text "+/-" at 13582.5,5203.49 h60
  text "REGISTRATION TOLERANCES:" at 11212.73,5198.49 h60
  text "METAL" at 12412.5,5198.49 h60
  text "5" at 12988.7,5198.49 h60
  text "3" at 13821.7,5198.49 h60
  text "MIL" at 13937.96,5198.49 h60
  text "IMPEDENCE CONTROLLED BOARD:NO" at 11245.5,5049.49 h60
  text "MATERIAL:" at 11121.96,4826.03 h60
  text "FR-4 High Tg" at 12108.4,4685.7 h60
  text "FR-408" at 11542.96,4677.13 h60
  text "OTHER" at 13030.96,4677.13 h60
  text "X" at 11946.5,4675.49 h60
  text "THICKNESS:" at 11123.5,4520.49 h60
  text "63 MIL (1.6mm) +/-10%" at 11782.5,4515.49 h60
  text "OTHER" at 13147.96,4510.13 h60
  text "X" at 11647.5,4507.49 h60
  text "TOLERANCE:" at 11196.73,4352.13 h60
  text "X" at 12036.03,4352.13 h60
  text "ANSI IPC-6012 TYPE 3 CLASS 2" at 12222.98,4352.13 h60
  text "OTHER +/-" at 12222.96,4196.13 h60
  text "BOW & TWIST:" at 11196.73,4039.13 h60
  text "X" at 12036.03,4039.13 h60
  text "ANSI IPC-6012 TYPE 3 CLASS 2" at 12222.98,4039.13 h60
  text "OTHER +/-" at 12222.96,3880.62 h60
  text "DRILLING:" at 11121.96,3742.13 h60
  text "REFERENCE:" at 11196.73,3625.13 h60
  text "X" at 11844.96,3625.13 h60
  text "AS SHOWN" at 12031.96,3625.13 h60
  text "X" at 12745.96,3625.13 h60
  text "NC_DRILL FILES" at 12882.96,3625.13 h60
  text "PTH MIN COPPER THICKNESS:" at 11196.73,3467.13 h60
  text "X" at 12546.96,3467.13 h60
  text "1MIL" at 12683.96,3467.13 h60
  text "OTHER" at 13180.96,3467.13 h60
  text "BOARD FINISH:" at 11121.96,3308.13 h60
  text "SILKSCREEN:" at 11277.18,3190.13 h60
  text "TOP" at 12351.96,3190.13 h60
  text "X" at 12735.96,3190.13 h60
  text "BOTTOM" at 12862.96,3190.13 h60
  text "SILKSCREEN COLOR:" at 11277.18,3023.13 h60
  text "X" at 12224.92,3023.13 h60
  text "WHITE" at 12351.96,3023.13 h60
  text "OTHER" at 12862.96,3023.13 h60
  text "SOLDER RESIST COLOR:" at 11277.18,2853.13 h60
  text "X" at 11844.92,2693.93 h60
  text "GREEN" at 11971.96,2693.93 h60
  text "BLUE" at 12562.96,2693.93 h60
  text "OTHER" at 13100.96,2693.93 h60
  text "IMMERSION GOLD (ENIG)" at 12182.96,2505.41 h60
  text "ENEPIG" at 13520.5,2502.13 h60
  text "SURFACE FINISH:" at 11121.96,2501.13 h60
  text "X" at 11996.01,2501.13 h60
  text "IMM. TIN/SILVER OR EQUIV" at 11451.5,2344.13 h60
  text "OTHER" at 12882.96,2344.13 h60
  text "ARRAY/PANEL:" at 11121.96,2165.13 h60
  text "CUT AND TRIM PER MECH LAYER 1" at 12182.96,2160.84 h60
  text "N.C. ROUTE" at 12182.96,2009.13 h60
  text "X" at 12861.96,2009.13 h60
  text "V. SCORE" at 13048.96,2009.13 h60
  text "CERTIFICATION:" at 11121.96,1872.13 h60
  text "MATERIALS AND WORKMANSHIP FOR ALL PCBS" at 11846.96,1872.13 h60
  text "TO MEET OR EXCEED THE REQUIREMENTS OF:" at 11846.96,1774.13 h60
  text "X" at 11473.46,1637.62 h60
  text "ANSI IPC-A-600F CLASS ->" at 11612.46,1637.62 h60
  text "X" at 13251.52,1637.62 h60
  text "2" at 13370.46,1637.62 h60
  text "1" at 13055.46,1636.13 h60
  text "3" at 13724.46,1636.13 h60
  text "X" at 11475.52,1478.13 h60
  text "UL 94V-0" at 11612.46,1478.13 h60
  text "X" at 12287.52,1478.13 h60
  text "RoHS" at 12424.46,1478.13 h60
  text "OTHER" at 13068.86,1478.13 h60
  text "PER ORDER" at 13465.92,1478.13 h60
  text "ADDITIONAL REQUIREMENTS:" at 11121.96,1337.13 h60
  text "MICROSECTION:" at 11196.73,1222.13 h60
  text "YES" at 12102.46,1222.13 h60
  text "REQUIRED" at 12963.96,1065.98 h60
  text "BARE BOARD ELEC. TEST:" at 11196.73,1063.13 h60
  text "NONE" at 12502.46,1063.13 h60
  text "X" at 12836.96,1063.13 h60
  text "PER ORDER" at 13555.96,1063.13 h60
  text "MANUFACTURER'S UL:" at 11196.73,906.13 h60
  text "RAIL" at 12362.46,901.84 h60
  text "METAL" at 12854.27,901.84 h60
  text "X" at 13229.5,901.49 h60
  text "SILK" at 13365.96,901.84 h60
  text "VIA`S TO BE TENTED:" at 11176.5,714.49 h60
  text "YES" at 12081.5,714.49 h60
M11 Gerber Information:
  lines w10: -507,-1235.68 6093,-1235.68 ; -507,-1032.34 6095,-1032.34 ; -507,-829.01 -507,-1439.01 3498,-1439.01 6095,-1439.01 6095,-829.01 -506.5,-829.01 -506.5,-1439.01 1069,-1439.01 ; 1958,-1439.01 1958,-829.01 ; 3225,-1032.34 3225,-829.01 ; 4065,-1032.34 4065,-829.01 ; 4687,-1445.51 4687,-1242.68
  text "ALL ARTWORK VIEWED FROM TOP SIDE" at -443.5,-961.18 h60
  text "BOARD #:" at 2033,-961.18 h60
  text ".PRJ_Number" at 2578.5,-961.18 h60
  text "REV:" at 3423,-961.18 h60
  text ".PCB_Rev" at 3714.5,-961.18 h60
  text "SVN REV:" at 4261,-961.18 h60
  text ".VersionControl_RevNumber" at 4767,-961.18 h60
  text "LAYER NAME =" at -443.5,-1164 h60
  text "TID #:" at 2033,-1164.51 h60
  text ".TID" at 2578.5,-1164.51 h60
  text "PLOT NAME =" at -443.5,-1369.85 h60
  text ".plot_File_Name" at 362,-1369.85 h60
  text "GENERATED    :" at 2035,-1369.85 h60
  text ".Print_Date" at 2904.5,-1369.85 h60
  text ".Print_Time" at 3633.5,-1369.85 h60
  text "TEXAS INSTRUMENTS" at 4898,-1369.85 h60
M12 Stackup:
  drawing of 191 lines, arcs and shapes, not listed
  text "Layer" at 9527,7459 h60
  text "Name" at 9936.91,7459 h60
  text "Material" at 10866.66,7459 h60
  text "Thickness" at 11726.42,7459 h60
  text "Constant" at 12376.26,7459 h60
  text "Board Layer Stack" at 12946.12,7459 h60
  text "1" at 9527,7339 h60
  text "Top Overlay" at 9936.91,7339 h60
  text "2" at 9527,7219 h60
  text "Top Solder" at 9936.91,7219 h60
  text "Solder Resist" at 10866.66,7219 h60
  text "0.40mil" at 11726.42,7219 h60
  text "3.5" at 12376.26,7219 h60
  text "3" at 9527,7099 h60
  text "Top Layer" at 9936.91,7099 h60
  text "Copper" at 10866.66,7099 h60
  text "1.40mil" at 11726.42,7099 h60
  text "4" at 9527,6979 h60
  text "Dielectric1" at 9936.91,6979 h60
  text "FR-4 High Tg" at 10866.66,6979 h60
  text "59.20mil" at 11726.42,6979 h60
  text "4.8" at 12376.26,6979 h60
  text "5" at 9527,6859 h60
  text "Bottom Layer" at 9936.91,6859 h60
  text "Copper" at 10866.66,6859 h60
  text "1.40mil" at 11726.42,6859 h60
  text "6" at 9527,6739 h60
  text "Bottom Solder" at 9936.91,6739 h60
  text "Solder Resist" at 10866.66,6739 h60
  text "0.40mil" at 11726.42,6739 h60
  text "3.5" at 12376.26,6739 h60
  text "7" at 9527,6619 h60
  text "Bottom Overlay" at 9936.91,6619 h60
M13 Component Bodies Top:
  text ".Layer_Name" at 362,-1164 h60
M14 Component Bodies Bottom:
  text ".Layer_Name" at 362,-1164 h60
M15 Courtyards Top:
  text ".Layer_Name" at 362,-1164 h60
M16 Courtyards Bottom:
  text ".Layer_Name" at 362,-1164 h60
Drill Drawing:
  circle w6: c3711.12,2780 r15
  circle w6: c3711.12,2780 r25
  lines w6: 3686.12,2505 3736.12,2505 3711.12,2455 3686.12,2505 ; 3686.12,2605 3686.12,2617.5 3698.62,2630 3686.12,2642.5 3686.12,2655 3698.62,2655 3711.12,2642.5 3723.62,2655 3736.12,2655 3736.12,2642.5 3723.62,2630 3736.12,2617.5 3736.12,2605 3723.62,2605 3711.12,2617.5 3698.62,2605 3686.12,2605 ; 3686.12,2905 3711.12,2917.5 3736.12,2905 3723.62,2930 3736.12,2955 3711.12,2942.5 3686.12,2955 3698.62,2930 3686.12,2905
  lines w15: 3618,2410 9920.26,2410 ; 3618,3010 9920.26,3010 ; 4168.88,2260 4168.88,3160 ; 4866.69,2260 4866.69,3160 ; 6212.29,2260 6212.29,3160 ; 6718.17,2260 6718.17,3160 ; 7451.97,2260 7451.97,3160 ; 8661.62,2260 8661.62,3160 ; 3618,2260 9920.26,2260 9920.26,3160 3618,3160 3618,2260
  text "Symbol" at 3708,3055 h72
  text "Hit Count" at 4213.88,3055 h72
  text "Finished Hole Size" at 4911.69,3055 h72
  text "Plated" at 6257.29,3055 h72
  text "Hole Type" at 6763.17,3055 h72
  text "Physical Length" at 7496.97,3055 h72
  text "Rout Path Length" at 8706.62,3055 h72
  text "1" at 4213.88,2905 h60
  text "120.00mil (3.048mm)" at 4911.69,2905 h60
  text "NPTH" at 6257.29,2905 h60
  text "Slot" at 6763.17,2905 h60
  text "600.00mil (15.240mm)" at 7496.97,2905 h60
  text "480.00mil (12.192mm)" at 8706.62,2905 h60
  text "4" at 4213.88,2755 h60
  text "43.31mil (1.100mm)" at 4911.69,2755 h60
  text "PTH" at 6257.29,2755 h60
  text "Round" at 6763.17,2755 h60
  text "5" at 4213.88,2605 h60
  text "39.37mil (1.000mm)" at 4911.69,2605 h60
  text "PTH" at 6257.29,2605 h60
  text "Round" at 6763.17,2605 h60
  text "9" at 4213.88,2455 h60
  text "15.00mil (0.381mm)" at 4911.69,2455 h60
  text "PTH" at 6257.29,2455 h60
  text "Round" at 6763.17,2455 h60
  text "19 Total" at 4213.88,2305 h60
  text "DRILL TABLE" at 5308,1499 h60
  text "FOR PTH +3/-3MIL" at 5308,1372 h60
  text "FOR NPTH +2/-2MIL" at 5307,1266 h60
  text "This is not impedence controlled board." at 5304,1150 h60
  text ".Layer_Name" at 362,-1164 h60

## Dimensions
0,0 to 0,1181.1 on M2 Board Dimensions
0,0 to 1460.63,0 on M2 Board Dimensions
-215,-705.51 to 785,-705.51 on M2 Board Dimensions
